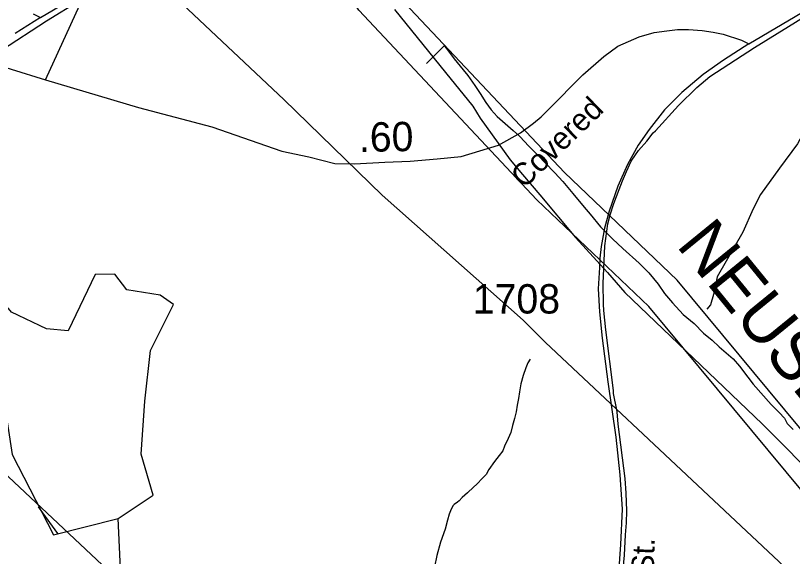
# Model space of a CAD drawing. Extents: x 2169602 to 2449496, y 721995 to 810662.
# Drawn here: x 2406538 to 2409846, y 762924 to 765226 of the extents above; entities that cross this region are included whole.
import ezdxf

# ---------------------------------------------------------------- set-up
doc = ezdxf.new("R2010")
doc.units = 0
doc.layers.add('Default', color=7, linetype='Continuous')

msp = doc.modelspace()

# ---------------------------------------------------------------- linework, layer by layer
at = {"layer": 'Default'}
for p, q in [((2408287.5, 765022), (2408363.4, 765097.7)), ((2406694.8, 763052.2), (2406635.7, 763134.7)), ((2406717.5, 763020.6), (2406694.8, 763052.2))]:
    msp.add_line(p, q, dxfattribs=at)
for points in [[(2410998.9, 759007.9), (2409859, 760053.1), (2407211.5, 762601.4), (2405778.5, 763946.8), (2405684, 764042.1), (2405083.2, 764574.5), (2404665, 764982.2), (2402074.2, 767418.4), (2399573.8, 769793.5), (2395074.1, 774085.3)], [(2414014.7, 758895), (2412874.9, 759940.3), (2410227.4, 762488.5), (2408794.3, 763834), (2408699.9, 763929.3), (2408099, 764461.7), (2407680.9, 764869.3), (2405090.1, 767305.6), (2402589.6, 769680.7), (2398089.9, 773972.5)], [(2410159.3, 762973.4), (2410100.6, 763007.4), (2409888.9, 763199.7), (2409234.4, 763987.9), (2408758.2, 764442), (2407999.7, 765249.5), (2407656.3, 765771), (2407540.9, 765953.4), (2407392.6, 766408.9), (2407364.2, 766691.4), (2407426.9, 767615.5), (2407442.4, 767719.9), (2407429.6, 768471.3)], [(2410315.4, 763110.2), (2410180.3, 763156.6), (2410007.7, 763313.3), (2409354.5, 764100), (2408874.7, 764557.6), (2408125.3, 765355.4), (2407768.8, 765856.5), (2407674.8, 766037.4), (2407554.6, 766437.5), (2407528.8, 766694.1), (2407590.1, 767597.9), (2407606.6, 767709.2), (2407593.6, 768474)], [(2403866.8, 766613.5), (2403937, 766587.8), (2403974.6, 766569), (2404031.1, 766533.1), (2404070.4, 766504), (2404137.1, 766445.9), (2404251.7, 766334.7), (2404357.8, 766242.3), (2404551, 766040.5), (2404734.9, 765886.5), (2404998.3, 765677.9), (2405109.5, 765604.3), (2405186.5, 765554.7), (2405273.3, 765510.3), (2405329.4, 765485.8), (2405484.1, 765417.9), (2405712.5, 765322.1), (2405856.5, 765250.3), (2406149.5, 765140.8), (2406372.3, 765043.5), (2406665.4, 764952.7)], [(2406644.3, 765218.5), (2406927.9, 765386.5), (2407310.5, 765612.7), (2407456, 765697.6), (2407699.7, 765837.3)], [(2409660.2, 765105.7), (2409943.7, 765273.7), (2410326.3, 765499.9), (2410471.8, 765584.7), (2410715.5, 765724.4)], [(2406665.4, 764952.7), (2406880.9, 765425)], [(2406478.4, 765079), (2406669.2, 765203.3), (2406813.9, 765293.1)], [(2406478.4, 765079), (2406669.2, 765203.3), (2406813.9, 765293.1)], [(2406612.7, 765234.3), (2406644.3, 765218.5)], [(2408152.2, 765252.3), (2408368.9, 764983.9), (2408484.8, 764840.3), (2408516.1, 764789.5), (2408644.5, 764611.9), (2408696.4, 764550.2), (2408770.4, 764462.4), (2408921.9, 764282), (2409058.9, 764132.4), (2409131.9, 764048), (2409716.5, 763487.7), (2410241.2, 762962.2)], [(2406644.3, 765218.5), (2406537, 765149.5)], [(2409119.7, 762809.2), (2409131.2, 762928.7), (2409135.2, 763016.2), (2409139, 763067.2), (2409140.5, 763118.1), (2409137.7, 763193.3), (2409133, 763255.3), (2409104.5, 763487), (2409099, 763539.9), (2409097.5, 763548), (2409084.7, 763617.1), (2409083.7, 763630.6), (2409050.7, 763888.7), (2409042.2, 763970), (2409041.2, 763998), (2409040.2, 764085.9), (2409047.5, 764246.3), (2409060, 764339.9), (2409070.5, 764377.9), (2409085.5, 764426.6), (2409108.2, 764486.5), (2409123, 764522.8), (2409138.7, 764562.1), (2409159.2, 764607), (2409161.5, 764610.2), (2409190, 764651.3), (2409225.5, 764691.5), (2409253.2, 764727.4), (2409263.5, 764736.2), (2409360.7, 764842.9), (2409438.7, 764920), (2409494.2, 764966.2), (2409685, 765090.5), (2409829.7, 765180.2), (2409899.7, 765223.8)], [(2409119.7, 762809.2), (2409131.2, 762928.7), (2409135.2, 763016.2), (2409139, 763067.2), (2409140.5, 763118.1), (2409137.7, 763193.3), (2409133, 763255.3), (2409104.5, 763487), (2409099, 763539.9), (2409097.5, 763548), (2409084.7, 763617.1), (2409083.7, 763630.6), (2409050.7, 763888.7), (2409042.2, 763970), (2409041.2, 763998), (2409040.2, 764085.9), (2409047.5, 764246.3), (2409060, 764339.9), (2409070.5, 764377.9), (2409085.5, 764426.6), (2409108.2, 764486.5), (2409123, 764522.8), (2409138.7, 764562.1), (2409159.2, 764607), (2409161.5, 764610.2), (2409190, 764651.3), (2409225.5, 764691.5), (2409253.2, 764727.4), (2409263.5, 764736.2), (2409360.7, 764842.9), (2409438.7, 764920), (2409494.2, 764966.2), (2409685, 765090.5), (2409829.7, 765180.2), (2409899.7, 765223.8)], [(2406665.4, 764952.7), (2407060.9, 764834.6), (2407373.3, 764752.5), (2407672.1, 764649.3), (2407786.4, 764624.2), (2407897.6, 764596.8), (2407981.1, 764595.1), (2408110.8, 764601.7), (2408218.9, 764606.7), (2408332.8, 764615.9), (2408435.1, 764626.7), (2408593.7, 764674.5), (2408688, 764727.3), (2408742.8, 764768), (2408776.1, 764795.5), (2408805.2, 764824.6), (2408954.1, 764974.3), (2409043.1, 765052.5), (2409102.9, 765095.7), (2409193.6, 765135.6), (2409257.6, 765153.9), (2409310.9, 765161.4), (2409356.6, 765167.2), (2409404, 765167.2), (2409461.4, 765163.1), (2409508.8, 765155.6), (2409550.4, 765146.4), (2409628.6, 765121.5), (2409660.2, 765105.7)], [(2410129.5, 765130.5), (2410054.7, 765051.1), (2410025.1, 765004.4), (2410004.9, 764953), (2410000.2, 764910.9), (2409976.8, 764873.5), (2409939.5, 764819), (2409895.9, 764733.3), (2409867.8, 764680.4), (2409791.5, 764576), (2409709.7, 764463.9), (2409678.6, 764403.2), (2409635, 764303.5), (2409525.2, 764113.5), (2409509.6, 764038.7), (2409497.1, 763995.1), (2409481.6, 763976.4)], [(2408363.4, 765097.7), (2408373.2, 765085.6), (2408405.4, 765041.8), (2408443.7, 764995.9), (2408463.4, 764971.8), (2408494.2, 764928.2), (2408516.1, 764894.5), (2408540.3, 764856.3), (2408562.7, 764824.6), (2408588.7, 764796.7), (2408622.8, 764766.8), (2408657, 764737.3), (2408684.9, 764711.2), (2408723.4, 764669.7), (2408765.9, 764628), (2408791.7, 764600.1), (2408833.8, 764556.4), (2408868.2, 764520.4), (2408910.7, 764468.6), (2408958.8, 764411), (2408984.9, 764381.1), (2409029, 764327.4), (2409079.4, 764275.6), (2409123.5, 764234), (2409194, 764172.3), (2409234.2, 764130.5), (2409274.4, 764083), (2409300.9, 764042.9), (2409334.9, 764003.3), (2409381, 763953.7), (2409427.6, 763915.9), (2409467.8, 763874.1), (2409503.7, 763844.3), (2409533.8, 763816.2), (2409594.1, 763765), (2409620.1, 763733), (2409656.6, 763687), (2409678.6, 763657.3), (2409755.1, 763569.9), (2409769.2, 763556), (2409789.3, 763535.9), (2409811.7, 763512.3), (2409823.7, 763490.2), (2409849.6, 763464.3)], [(2409660.2, 765105.7), (2409552.9, 765036.7), (2409465.5, 764976), (2409374.9, 764899.4), (2409301.7, 764824.6), (2409235.2, 764741.4), (2409189.4, 764674.9), (2409143.7, 764592.6), (2409102.1, 764500.3), (2409065.5, 764393), (2409046.4, 764321.5), (2409031.4, 764243.3), (2409026.4, 764193.4), (2409023.9, 764154.3), (2409019, 764062.8), (2409024.8, 763964.7), (2409035.6, 763853.2), (2409060.5, 763666.9), (2409093.8, 763431.6), (2409110.4, 763271.1), (2409120.4, 763125.5), (2409113.8, 762975), (2409100.5, 762791.2)], [(2406975.2, 763085.4), (2407124.3, 763184), (2407073.3, 763358.9), (2407088.4, 763584.9), (2407112.4, 763800.9), (2407211.3, 763995.8), (2407153.4, 764036.3), (2407011.3, 764058.9), (2406960.3, 764125.5), (2406877.4, 764123.9), (2406762.4, 763883.5), (2406670.3, 763892), (2406520.4, 763963.9), (2406293.3, 764237.5), (2406252.4, 764264.6), (2406202.4, 764246), (2406202.4, 764131.1), (2406346.4, 763839.5), (2406355.4, 763704.8), (2406397.4, 763638.4), (2406489.3, 763580.7), (2406523.3, 763357), (2406700.3, 763015.5), (2406975.2, 763085.4)], [(2408728.7, 763763.9), (2408718.8, 763748), (2408710.9, 763726), (2408699.2, 763693.7), (2408689.3, 763657.9), (2408683.6, 763623.9), (2408679.9, 763595.7), (2408673.9, 763567.8), (2408670, 763539.5), (2408662.5, 763511.5), (2408654.5, 763481.4), (2408646.5, 763451.8), (2408635, 763425.6), (2408620.6, 763393.7), (2408613, 763373.3), (2408597, 763353.4), (2408577.4, 763327.2), (2408553.4, 763293.2), (2408541.5, 763273), (2408525.7, 763257.2), (2408501.7, 763230.8), (2408487.8, 763218.7), (2408461.7, 763194.6), (2408440.2, 763174.4), (2408426.2, 763160.2), (2408420.1, 763154.3), (2408406.1, 763144.2), (2408402, 763140.4), (2408392.2, 763124.4), (2408384.2, 763104.1), (2408376.8, 763078.1), (2408367.2, 763040.2), (2408347.1, 762984), (2408331.5, 762928), (2408321.9, 762879.9)], [(2407028.3, 762526.6), (2406994.3, 762658.5), (2406975.2, 763085.4)]]:
    msp.add_lwpolyline(points, dxfattribs=at)

# ---------------------------------------------------------------- texts
for s, height, rotation, p in [('Covered', 95, 44.0646, (2408703.2, 764486.4)), ('.60', 125, 0.9779, (2408000.8, 764645.6)), ('NEUSE', 210, 309.1609, (2409347.6, 764247.4)), ('St.', 95, 87.9022, (2409254.8, 762846))]:
    msp.add_text(s, height=height, rotation=rotation, dxfattribs=at).set_placement(p)
msp.add_text('1708', height=125, dxfattribs=at).set_placement((2408484.7, 763957.8))

doc.saveas('drawing.dxf')
